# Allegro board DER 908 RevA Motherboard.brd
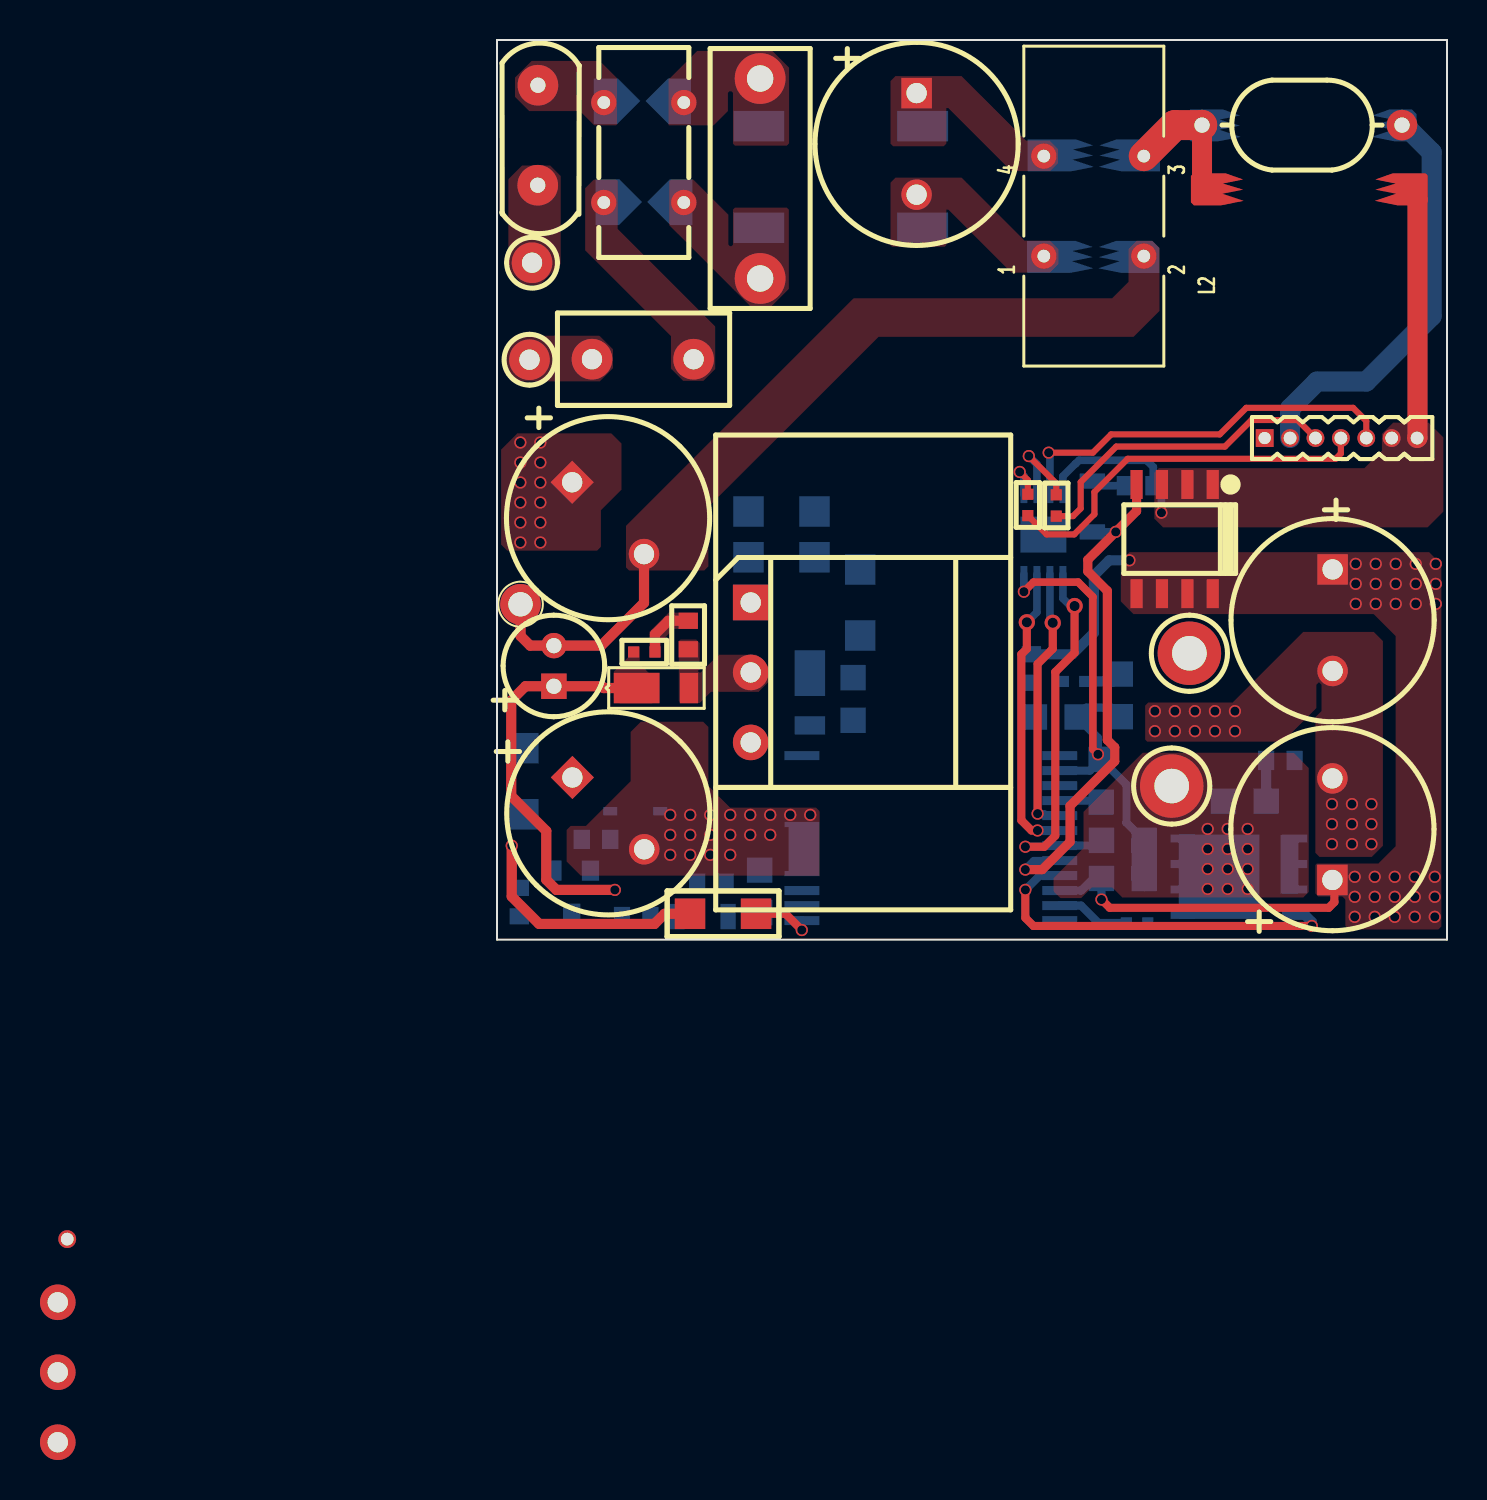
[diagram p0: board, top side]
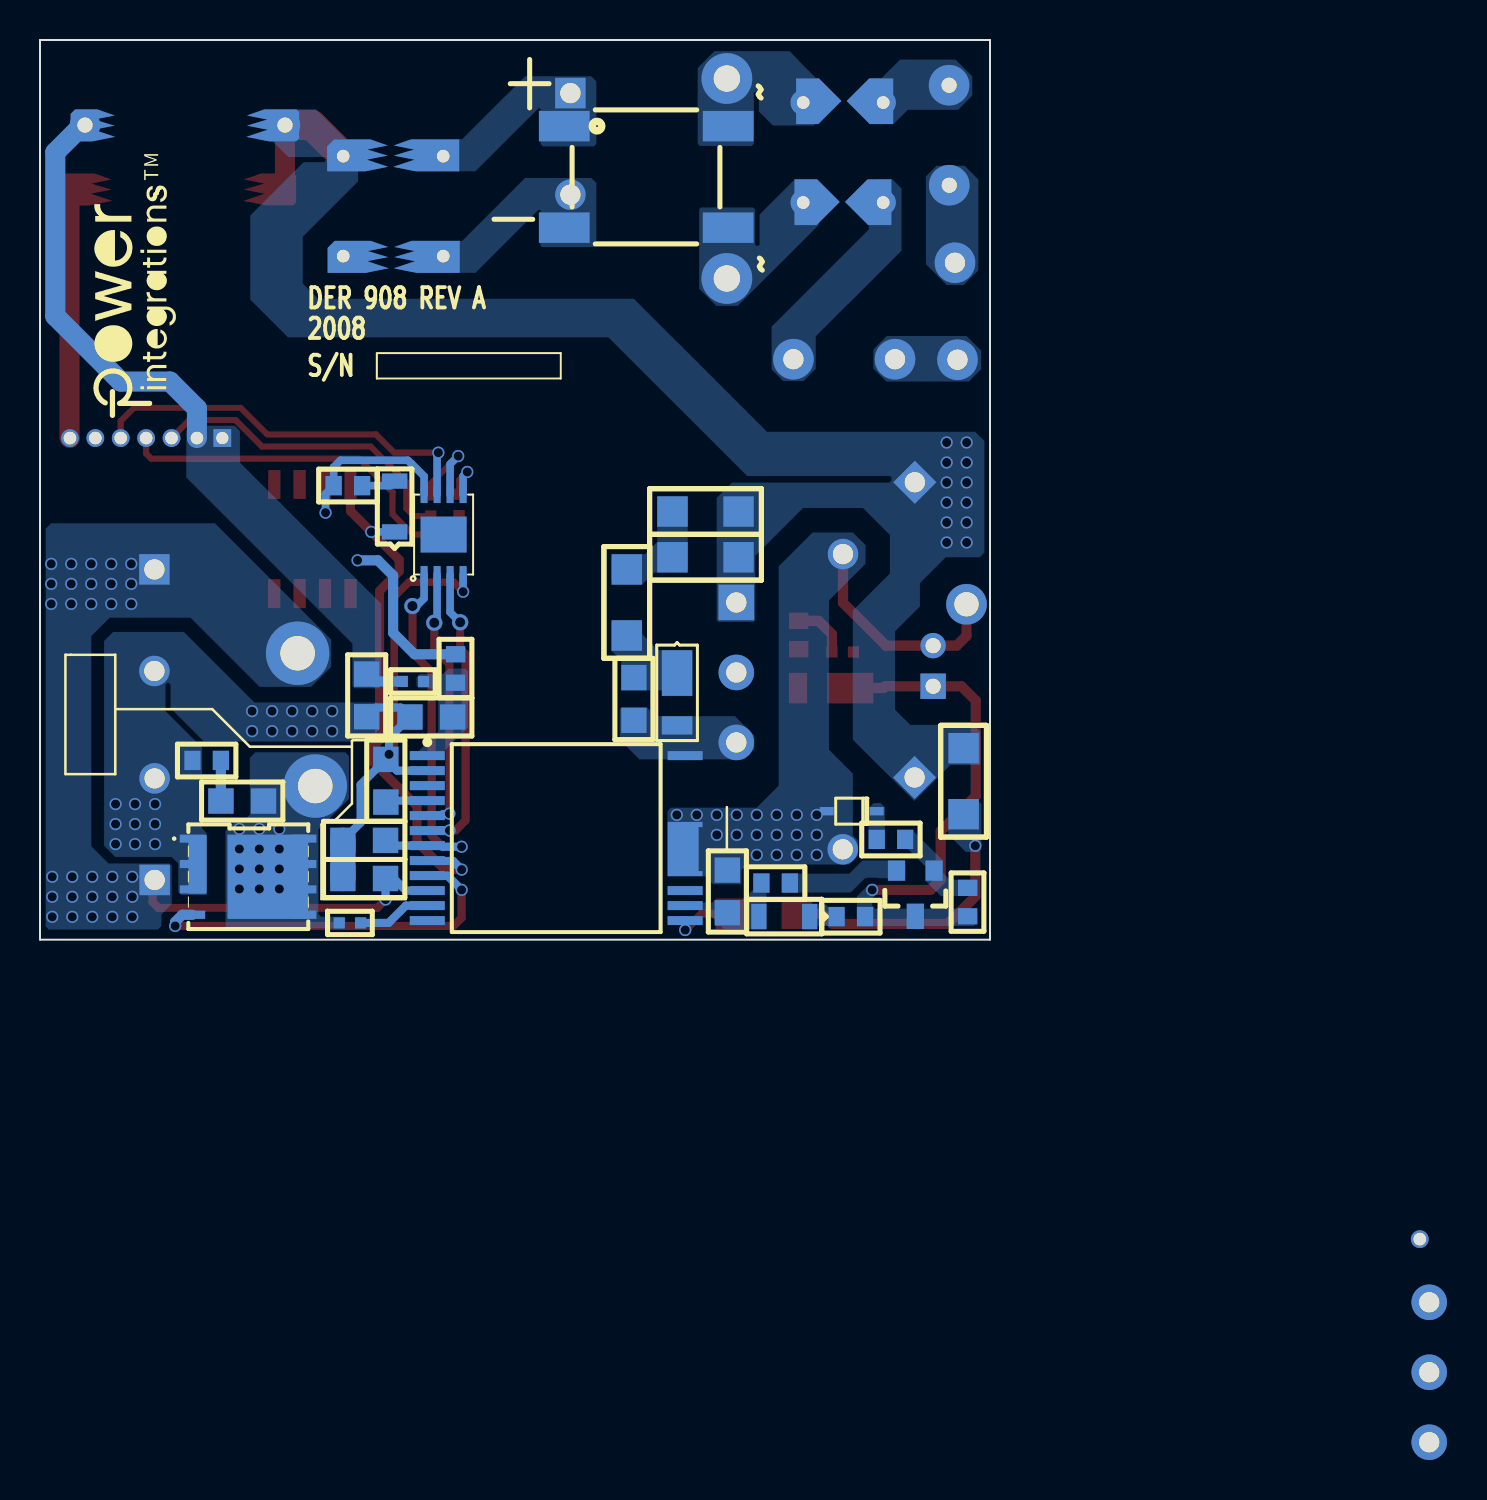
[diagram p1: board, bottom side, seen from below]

Outline 47.5 x 45 mm; copper layers: TOP, BOTTOM. Coordinates in mm from the lower left corner of the outline.
Outline path: 0,45 0,0 47.5,0 47.5,45 0,45

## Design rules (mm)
constraint set DEFAULT: min track width 0.508

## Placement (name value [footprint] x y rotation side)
BR1  TBS30M-TP  [PISMD_4-TBS]  21.73 40.69 90 bottom
C1  0.1 uF  [PINPXCAPRAD5X13X11P1MM040]  13.16 33.07 90 top
C2  15 uF  [PIPOLCAPCYLD400LS200040]  20.98 42.34 270 top
C3  15 uF  [PIPOLCAPCYLD400LS200040]  3.76 22.88 315 top
C4  15 uF  [PIPOLCAPCYLD400LS200040]  3.77 8.11 315 top
C5  22  uF  [PIPOLCAPCLYD200LS80030]  2.84 12.67 90 top
C6  2.2 nF  [PISMC1206]  15.88 21.41 180 bottom
C7  47 pF  [PISMC0805]  17.81 13.11 270 bottom
C8  56 pF  [PISMC0603]  9.56 15.95 270 top
C9  4.7 uF  [PISMC0805]  13.13 1.35 90 bottom
C10  470 pF  [PINPCAPRAD7MMXLS10MM030]  35.25 40.74 0 top
C11  470 uF  [PIPOLCAPCYLD400LS200040]  41.77 2.99 90 top
C12  470 uF  [PIPOLCAPCYLD400LS200040]  41.78 18.52 270 top
C13  1000 pF  [PISMC0603]  39.88 8.97 180 bottom
C14  2.2 uF  [PISMC0805]  30.21 9.02 270 bottom
C15  4.7 uF  [PISMC0805]  29 11.14 180 bottom
C16  2.2 uF  [PISMC0805]  32.36 3.06 180 bottom
C17  2.2 uF  [PISMC0805]  32.36 4.97 180 bottom
D1  DFLR1200-7  [PISMDDFLR120012]  6.96 12.59 180 top
D2  DFLR1600-7  [PISMDDFLR120012]  15.65 13.36 90 bottom
D3  BAV21WS-7-F  [PISMSOD323]  29.77 20.4 90 bottom
F1  2 A  [PI_RST_MICROFUSE]  9.83 29.03 180 top
FL1  Hole_70mils  [PI_HOLE_70MIL]  34.62 14.3 0 top
FL2  Hole_70mils  [PI_HOLE_70MIL]  33.74 7.66 0 top
FL3  Hole_50mils  [PI_HOLE_50MIL]  1.18 16.77 0 top
J2  CON8  [PI_HDR_1P27MM_8PIN]  38.38 25.09 0 top
L1  750 uH  [PI_4P_LS5W4P5XD10P5MMD40]  7.34 39.37 0 top
L2  19.8 mH  [PI_TOROID_CMC15X7_12_34V]  26.34 34.19 90 top
NOREF  -  []  -150.78 54.23 0 top
NOREF#2  -  []  -228.6 -144.78 0 top
NOREF#3  -  []  0 45 0 top
NOREF#4  -  []  47.5 0 90 top
NOREF#5  -  []  45.26 26.11 90 bottom
Q1  MMBTA06LT1G  [PISMSOT23123_1]  4.67 3.45 0 bottom
Q2  AONS62922  [PISMPQFN5X6B]  39.88 5.05 270 bottom
Q3  AO4354  [PISMSO8]  35.79 22.77 180 top
R1  2.00 M  [PISMR1206]  1.32 6.27 90 bottom
R2  1.80 M  [PISMR1206]  12.95 1.3 180 top
R3  1.00 M  [PISMR1206]  12.57 19.13 0 bottom
R4  4.7  [PISMR1206]  18.16 15.21 90 bottom
R5  100  [PISMR0402]  6.83 14.39 0 top
R6  64.9 k  [PISMR0603]  1.12 2.59 270 bottom
R7  0.0  [PISMR0603]  5.66 5.02 180 bottom
R8  2.55 k  [PISMR0603]  11.43 2.83 180 bottom
R9  47  [PISMR0603]  7.67 1.16 180 bottom
R10  47  [PISMR0402]  32.54 0.84 180 bottom
R11  10  [PISMR0805]  38.46 6.93 180 bottom
R12  0.009  [PISMR0805]  31.17 11.15 90 bottom
R13  422 k (DNP)  [PISMR0603]  26.72 14.27 270 bottom
R14  10  [PISMR0402]  29.39 12.92 180 bottom
R15  100  [PISMR0603]  31.39 22.71 0 bottom
R16  22  [PISMR0402]  27.97 21.18 90 top
R17  22  [PISMR0402]  26.54 21.21 90 top
RT1  2.5  [PI_RAD150X300LS200D030]  2.04 37.73 89.9 top
T1  ATQ23.7/14  [PI_BOBBIN_ATQ23_7_H_6P]  18.31 13.37 0 top
TP1  WHT  [PITPKEYSTONE100X100]  1.63 29.01 0 top
TP2  BLK  [PITPKEYSTONE100X100]  1.75 33.86 270 top
U1  INN3378C-H302  [PI_IC_INSOP_24D]  28.14 9.21 180 bottom
U2  VP302  [PI_SM_DFN-8]  28.3 18.26 180 bottom
VR1  MM3Z9V1C  [PISMSOD323F]  5.66 6.43 0 bottom
VR2  BZX384-C36,115  [PISMSOD323]  9.02 1.16 0 bottom

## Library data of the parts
BR1 = DIODE BRIDGE_+-~~
C1 = CAP NP: alternate symbols: (pinpxcaprad5x13x11p1mm040h)
C2-C4 = CAP POL: alternate symbols: (pipolcapcyld400ls200040800h)
C5 = CAP POL: alternate symbols: (pipolcapclyd200ls80030h)
C6-C10 C13-C17 = CAP NP
C11 C12 = CAP POL
D1-D3 = DIODE
F1 = FUSE: alternate symbols: (pirstmicrofusehoz)
FL1-FL3 = FlyingLead
J2 = CON8
L1 L2 = TORRID 4P_12_43a
Q1 = NPN_BEC
Q2 Q3 = FET_N_SGD_123_4_5678
R1-R8 R10-R17 = R
R9 = R: alternate symbols: (pismr0603_1)
RT1 = THERMISTOR: alternate symbols: (pirad400x300ls200040_h)
T1 = BATQ23_7_6P/GENERIC
TP1 TP2 = TESTPOINT
U1 = InnoPro_p15
U2 = VP302
VR1 VR2 = DIODE_ZENER

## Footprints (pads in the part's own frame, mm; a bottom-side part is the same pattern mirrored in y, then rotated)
PI_4P_LS5W4P5XD10P5MMD40
  round 1.27 hole 0.635: 1(-2,-2.5) 2(2,-2.5) 3(2,2.5) 4(-2,2.5)
PI_BOBBIN_ATQ23_7_H_6P
  rect 1.778x1.778 hole 1.016: 1(-5.626,3.5)
  round 1.778 hole 1.016: 2(-5.626,0) 3(-5.626,-3.5) 4(-40.272,-38.501) 5(-40.272,-35.001) 6(-40.272,-31.501)
PI_HDR_1P27MM_8PIN
  rect 0.889x0.889 hole 0.61: 1(0,0)
  round 0.889 hole 0.635: 2(1.27,0) 3(2.54,0) 4(3.81,0) 5(5.08,0) 6(6.35,0) 7(7.62,0) 8(-59.873,-40.066)
PI_HOLE_50MIL
  round 2.032 hole 1.219: 1(0,0)
PI_HOLE_70MIL
  round 3.175 hole 1.727: 1(0,0.025)
PI_IC_INSOP_24D
  rect 1.75x0.45 smd: 1(0,0) 2(0,-0.749) 3(0,-1.501) 4(0,-2.25) 5(0,-3) 6(0,-3.749) 7(0,-4.501) 8(0,-5.25) 9(0,-6) 10(0,-6.749) 11(0,-7.501) 12(0,-8.25) 13(12.89,-8.25) 14(12.89,-7.501) 15(12.89,-6.749) 24(12.89,0)
  custom 0.437x0.437 smd: 16(12.89,-4.671)
PI_RAD150X300LS200D030
  round 2.032 hole 0.762: 1(0,0) 2(5.001,0)
PI_RST_MICROFUSE
  round 2.032 hole 1.016: 1(0,0) 2(5.08,0)
PI_SM_DFN-8
  rect 0.35x0.851 smd: 1(0,0) 2(0.65,0) 3(1.301,0) 4(1.951,0) 5(1.951,4) 6(1.301,4) 7(0.65,4) 8(0,4)
  rect 2.301x1.801 smd: 9(0.975,1.999)
PI_TOROID_CMC15X7_12_34V
  round 1.27 hole 0.635: 1(0,-1) 2(0,-6) 3(5,-6) 4(5,-1)
PINPCAPRAD7MMXLS10MM030
  round 1.524 hole 0.762: 1(0,0) 2(10,0)
PINPXCAPRAD5X13X11P1MM040
  round 2.54 hole 1.321: 1(0,0) 2(10,0)
PIPOLCAPCLYD200LS80030
  rect 1.27x1.27 hole 0.762: 1(0,0)
  round 1.27 hole 0.762: 2(2.032,0)
PIPOLCAPCYLD400LS200040
  rect 1.524x1.524 hole 1.016: 1(0,0)
  round 1.524 hole 1.016: 2(5.08,0)
PISMC0603
  rect 0.813x0.965 smd: 1(0,0) 2(1.422,0)
PISMC0805
  rect 1.27x1.27 smd: 1(0,0) 2(2.134,0)
PISMC1206
  rect 1.524x1.524 smd: 1(0,0) 2(3.302,0)
PISMD_4-TBS
  rect 1.524x2.54 smd: 1(0,-0.449) 2(-5.08,-0.449) 3(0,-8.644) 4(-5.08,-8.644)
PISMDDFLR120012
  rect 2.286x1.524 smd: 1(-0.025,0)
  rect 0.914x1.524 smd: 2(-2.642,0)
PISMPQFN5X6B
  rect 0.406x1.27 smd: 1(0,0) 2(1.27,0) 3(2.54,0) 4(3.81,0)
  rect 0.406x1.219 smd: 5(3.81,5.588) 6(2.54,5.588) 7(1.27,5.588) 8(0,5.588)
PISMR0402
  rect 0.559x0.559 smd: 1(0,0) 2(1.067,0)
PISMR0603
  rect 0.813x0.965 smd: 1(0,0) 2(1.422,0)
PISMR0805
  rect 1.27x1.27 smd: 1(0,0) 2(2.134,0)
PISMR1206
  rect 1.524x1.524 smd: 1(0,0) 2(3.302,0)
PISMSO8
  rect 0.61x1.448 smd: 1(0,0) 2(1.27,0) 3(2.54,0) 4(3.81,0) 5(3.81,5.461) 6(2.54,5.461) 7(1.27,5.461) 8(0,5.461)
PISMSOD323
  rect 0.762x1.27 smd: 1(0,0) 2(2.54,0)
PISMSOD323F
  rect 0.701x0.419 smd: 1(0,0) 2(2.5,0)
PISMSOT23123_1
  rect 0.864x1.016 smd: 1(-1.88,0) 2(0,0)
  rect 0.864x1.27 smd: 3(-0.94,2.286)
PITPKEYSTONE100X100
  round 2.032 hole 1.016: 1(0,0)

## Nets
VBUS: J2.6 J2.7 Q3.1 Q3.2 Q3.3(S3) R15.2 U2.8
CC1: J2.3 R16.1
CC2: J2.4 R17.1
NC3: U1.3
NTC: J2.5 U2.7
RTN: C10.2 J2.1 J2.2 R12.2 R14.1
S: C11.2 C12.2 C13.1 C14.1 C15.1 C16.1 C17.1 Q2.1 Q2.2 Q2.3(S3) R12.1 U1.2 U2.4
V-PIN: R2.1 U1.13
N12237519: F1.2 TP1.1
N12237523: RT1.1 TP2.1
N12237527: BR1.1 C2.1 L2.4
N12237547: C3.1 C4.1 C6.2 C10.1 L2.3 R1.2 R3.1 T1.1
N12237619: F1.1 L1.1
N12237623: L1.4 RT1.2
N12237649: BR1.3 C1.2 L1.3
N12237657: BR1.4 C1.1 L1.2
N12237771: BR1.2 C2.2 L2.1
N12237803: C3.2 C4.2 C5.2 C9.2 FL3.1 L2.2 U1.16 VR1.2
N12645578: C5.1 D1.1 Q1.3 R5.1 R6.2 R9.2
N12645654: Q1.1 R6.1 R7.2
N12645698: R7.1 VR1.1
N12646808: Q1.2(EMITTER) R8.2
N12647032: C8.2 D1.2 T1.2
N12647250: C7.2 D2.2 T1.3 U1.24
N12647255: C7.1 D2.1 R4.1
N12647291: C6.1 R3.2 R4.2
N12648519: C8.1 R5.2
N12649378: C9.1 R8.1 U1.14 VR2.2
N12649481: R9.1 VR2.1
N12651364: R1.1 R2.2
N12652887: C11.1 C12.1 C16.2 FL1.1 Q3.5 Q3.6 Q3.7 Q3.8 R13.1 U1.10(VOUT)
N12652989: D3.1 Q3.4 U1.8
N12653013: D3.2 R15.1
N12653157: FL2.1 Q2.5 Q2.6 Q2.7 Q2.8 R10.1 R11.2
N12653279: Q2.4 U1.9
N12653331: R10.2 U1.11
N12653381: C15.2 R13.2 R14.2 U1.1
N12665660: C17.2 U1.7 U2.1(VCC)
N12665712: R16.2 U2.6
N12665748: R17.2 U2.5
N12666228: U1.5 U2.2
N12666235: U1.6 U2.3
N12666360: C14.2 U1.4
N12689323: C13.2 R11.1

Pads without a net: J2 8; T1 4 5 6; U1 12 15; U2 9

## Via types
v1: diameter 0.61, hole 0.457, TOP to BOTTOM, 109 vias
v2: diameter 0.813, hole 0.508, TOP to BOTTOM, 3 vias

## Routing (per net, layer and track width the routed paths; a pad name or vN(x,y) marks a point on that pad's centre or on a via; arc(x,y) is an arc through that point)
VBUS: length 21
  TOP w1: J2.7 46.02,25.11 46.02,37.03 45.57,37.49
  BOTTOM w0.381: U2.8 28.3,23.18 28.93,23.81 28.94,23.81 29.11,23.98 32.48,23.98 32.82,23.64 R15.2 33.22,22.3 v1(33.22,21.36)
CC1: length 16.1
  TOP w0.305: J2.3 40.92,25.09 40.03,25.99 37.73,25.99 36.4,24.66 30.96,24.66 29.18,22.89 29.18,21.56 28.8,21.18 R16.1
CC2: length 19.1
  TOP w0.305: R17.1 27.48,20.27 28.86,20.27 29.87,21.28 29.87,22.39 31.54,24.05 41.93,24.05 42.19,24.31 J2.4
NTC: length 20.1
  TOP w0.305: v1(27.58,24.36) 29.79,24.36 30.71,25.27 36.14,25.27 37.47,26.6 42.8,26.6 43.46,25.94 J2.5
  BOTTOM w0.381: U2.7 27.65,24.3 v1(27.58,24.36)
RTN: length 22.5
  BOTTOM w0.508: R12.2 30.8,12.92 R14.1
  BOTTOM w1: J2.2 39.65,26.57 41,27.91 43.46,27.91 46.74,31.19 46.74,39.38 45.4,40.71
S: length 27.1
  TOP w0.381: v1(26.34,17.4) 26.82,17.88 29.06,17.88 29.79,17.14 29.79,9.53 v1(30.05,9.27)
  BOTTOM w0.381: U2.4 v1(26.34,17.4)
  BOTTOM w0.406: C14.1 29.65,8.45 28.14,8.45 U1.2 ; C14.1 31.47,7.75 31.47,5.85 C17.1 ; C14.1 30.21,9.11 v1(30.05,9.27) 30.05,10.09 C15.1 29,11.15 29.46,11.61 30.71,11.61 R12.1
  BOTTOM w1.27: C17.1 C16.1
  vias: v1(32.89,11.43) v1(32.89,10.43) v1(33.89,11.43) v1(33.89,10.43) v1(34.89,11.43) v1(34.89,10.43) v1(35.9,11.43) v1(35.9,10.43) v1(36.9,11.43) v1(36.9,10.43) v1(41.75,6.78) v1(41.75,5.78) v1(41.75,4.78) v1(42.75,6.78) v1(42.75,5.78) v1(42.75,4.78) v1(43.72,6.78) v1(43.72,5.78) v1(43.72,4.78)
V-PIN: length 3.1
  TOP w0.406: v1(15.24,0.48) 14.43,1.3 R2.1
  BOTTOM w0.406: U1.13 15.25,0.95 15.25,0.95 15.25,0.49 v1(15.24,0.48)
N12237547: length 6.9
  TOP w1: C10.1 35.25,37.98 35.66,37.57
  TOP w1.5: C10.1 33.89,40.74 L2.3
  vias: v1(1.17,24.87) v1(1.17,23.87) v1(1.17,22.87) v1(1.17,21.87) v1(1.17,20.87) v1(1.17,19.87) v1(2.17,24.87) v1(2.17,23.87) v1(2.17,22.87) v1(2.17,21.87) v1(2.17,20.87) v1(2.17,19.87)
N12237803: length 11.3
  TOP w0.508: C3.2 7.35,19.29 7.35,16.85 5.21,14.71 C5.2 1.66,14.71 1.18,15.19 FL3.1
  vias: v1(8.66,6.24) v1(8.66,5.24) v1(8.66,4.24) v1(9.66,6.24) v1(9.66,5.24) v1(9.66,4.24) v1(10.66,6.24) v1(10.66,5.24) v1(10.66,4.24) v1(11.66,6.24) v1(11.66,5.24) v1(11.66,4.24) v1(12.66,6.24) v1(12.66,5.24) v1(13.66,6.24) v1(13.66,5.24) v1(14.66,6.24) v1(15.66,6.24)
N12645578: length 19.9
  TOP w0.508: v1(5.89,2.49) 2.97,2.49 2.46,3 2.46,5.44 0.71,7.19 0.71,11.96 1.42,12.67 C5.1 5.24,12.67 5.33,12.59 D1.1
N12648519: length 2.8
  TOP w0.508: C8.1 8.57,15.95 7.9,15.28 R5.2
N12651364: length 12.2
  TOP w0.508: R2.2 8.38,1.3 7.87,0.79 2.11,0.79 0.74,2.16 v1(0.74,4.7)
N12652887: length 25
  TOP w0.406: v1(30.22,2.01) 30.64,1.59 41.58,1.59 41.87,1.88 41.87,2.89 C11.1
  BOTTOM w0.406: v1(30.22,2.01) C16.2 29.81,3.06 29.21,2.46 U1.10
  BOTTOM w0.508: v1(31.62,18.97) 30.61,18.97 29.84,18.21 29.84,15.35 28.77,14.27 R13.1
  vias: v1(42.94,18.8) v1(42.94,17.8) v1(42.94,16.79) v1(42.89,3.14) v1(42.89,2.14) v1(42.89,1.14) v1(43.94,18.8) v1(43.94,17.8) v1(43.94,16.79) v1(43.89,3.14) v1(43.89,2.14) v1(43.89,1.14) v1(44.94,18.8) v1(44.94,17.8) v1(44.94,16.79) v1(44.89,3.14) v1(44.89,2.14) v1(44.89,1.14) v1(45.94,18.8) v1(45.94,17.8) v1(45.94,16.79) v1(45.89,3.14) v1(45.89,2.14) v1(45.89,1.14) v1(46.94,18.8) v1(46.94,17.8) v1(46.94,16.79) v1(46.89,3.14) v1(46.89,2.14) v1(46.89,1.14)
N12652989: length 26.3
  TOP w0.457: Q3.4 31.98,21.44 v1(30.94,20.4) 29.54,19 29.54,18.42 30.52,17.44 30.52,9.99 30.89,9.62 30.89,8.92 28.65,6.69 28.65,4.89 27.26,3.51 v1(26.42,3.51)
  BOTTOM w0.381: D3.1 v1(30.94,20.4)
  BOTTOM w0.406: U1.8 28.12,3.94 27.66,3.94 27.66,3.94 26.85,3.94 v1(26.42,3.51)
N12653013: length 1.7
  BOTTOM w0.381: D3.2 30,22.71 R15.1
N12653157:
  vias: v1(35.53,5.54) v1(35.53,4.54) v1(35.53,3.54) v1(35.53,2.54) v1(36.54,5.54) v1(36.54,4.54) v1(36.54,3.54) v1(36.54,2.54) v1(37.53,5.54) v1(37.53,4.54) v1(37.53,3.54) v1(37.53,2.54)
N12653279: length 19.1
  TOP w0.406: v1(40.74,0.69) 26.82,0.69 26.42,1.09 v1(26.42,2.49)
  BOTTOM w0.406: U1.9 28.13,3.2 27.13,3.2 v1(26.42,2.49)
  BOTTOM w0.508: v1(40.74,0.69) 40.74,0.89 40.39,1.24 Q2.4
N12653331: length 3.7
  BOTTOM w0.406: R10.2 30.07,0.84 29.2,1.7 U1.11
N12665660: length 19.5
  TOP w0.406: v1(26.42,4.65) 27.36,4.65 27.91,5.2 27.91,13.39 28.88,14.35 v2(28.88,16.69)
  BOTTOM w0.381: U2.1 28.3,17.07 28.68,16.69 v2(28.88,16.69)
  BOTTOM w0.406: C17.2 29.96,4.7 U1.7 28.12,4.69 27.4,4.69 27.36,4.65 v1(26.42,4.65)
N12665712: length 4.6
  TOP w0.305: R16.2 27.97,22.81 v1(26.59,24.19)
  BOTTOM w0.381: v1(26.59,24.19) 27,23.78 U2.6
N12665748: length 2.5
  TOP w0.305: v1(26.14,23.39) 26.54,22.99 R17.2
  BOTTOM w0.381: v1(26.14,23.39) 26.34,23.19 U2.5
N12666228: length 13.5
  TOP w0.406: v1(27.03,6.3) 27.03,13.79 27.79,14.55 v2(27.79,15.85)
  BOTTOM w0.381: U2.2 27.65,15.99 v2(27.79,15.85)
  BOTTOM w0.406: v1(27.03,6.3) 27.06,6.27 27.36,6.27 27.43,6.21 U1.5
N12666235: length 14.7
  TOP w0.406: v1(27.03,5.46) 26.73,5.46 26.22,5.97 26.22,14.27 26.49,14.55 v2(26.49,15.88)
  BOTTOM w0.381: U2.3 27,16.38 v2(26.49,15.88)
  BOTTOM w0.406: U1.6 27.03,5.46 v1(27.03,5.46)
N12666360: length 2.1
  BOTTOM w0.406: U1.4 30.14,6.95 C14.2
N12689323: length 2
  BOTTOM w0.508: R11.1 C13.2

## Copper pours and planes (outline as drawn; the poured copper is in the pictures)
VBUS on TOP (solid shape): 46.53,38.23 46.53,36.88 46.38,36.73 45.04,36.73 43.89,36.95 44.96,37.31 43.92,37.51 44.93,37.82 43.92,38.02 44.78,38.33 46.43,38.33
VBUS on TOP: 32.87,23.36 32.87,21.06 33.3,20.62 46.53,20.62 47.32,21.41 47.32,25.12 46.58,25.86 44.81,25.86 44.25,25.3 44.25,24.46 43.37,23.58 33.1,23.58
RTN on BOTTOM (solid shape): 45.97,41.3 45.97,40.13 45.77,39.93 45.77,39.93 44.88,39.93 43.74,40.15 44.81,40.51 43.77,40.71 44.78,41.02 43.77,41.22 44.63,41.53 45.74,41.53
RTN on BOTTOM: 31.78,12.57 31.88,12.67 31.88,14.81 40.18,23.11 40.18,25.45 39.93,25.7 37.77,25.7 37.5,25.44 37.5,23.86 30.43,16.79 30.43,12.7 30.56,12.57
S on BOTTOM (solid shape): 40.08,2.31 39.17,2.31 39.17,5.23 40.08,5.23
S on TOP: 40.92,11.13 40.92,4.34 41.12,4.14 43.74,4.14 44.3,4.7 44.3,14.94 43.84,15.39 40.31,15.39 36.78,11.86 32.56,11.86 32.41,11.71 32.41,10.01 32.51,9.91 39.29,9.91 40.97,11.58 40.97,12.75 41.1,12.88 41.22,12.75 41.22,11.43
S on BOTTOM: 39.17,2.24 40.44,2.24 40.59,2.39 40.59,3.81 40.92,4.14 43.74,4.14 44.3,4.7 44.3,14.94 43.84,15.39 40.31,15.39 36.78,11.86 30.53,11.86 30.53,10.52 31.14,9.91 39.29,9.91 40.97,11.58 40.97,12.75 41.1,12.88 41.22,12.75 41.22,11.43 39.4,9.6 39.4,5.56 39.17,5.33
N12237519 on TOP: 1.14,30.21 0.41,29.48 0.41,28.54 1.02,27.93 5.14,27.93 5.8,28.58 5.8,29.52 5.12,30.21
N12237519 on BOTTOM: 1.17,30.19 0.44,29.46 0.44,28.53 1.06,27.91 5.18,27.91 5.84,28.57 5.84,29.51 5.16,30.19
N12237523 on TOP: 2.65,38.72 1.26,38.72 0.57,38.04 0.57,33.49 1.31,32.75 2.15,32.75 3.19,33.79 3.19,38.19
N12237523 on BOTTOM: 2.67,38.71 1.27,38.71 0.58,38.02 0.58,33.48 1.32,32.74 2.16,32.74 3.2,33.78 3.2,38.18
N12237527 on BOTTOM (solid shape): 29.81,39.72 28.8,39.52 29.81,39.22 28.77,39.01 29.84,38.66 28.69,38.43 26.53,38.43 26.53,40.03 28.95,40.03
N12237527 on TOP: 22.47,41.59 22.57,41.59 25.72,38.44 27.67,38.44 28.05,38.82 28.05,39.54 27.62,39.97 26.45,39.97 23.23,43.19 19.93,43.19 19.67,42.94 19.67,39.81 19.8,39.69 22.34,39.69 22.47,39.81
N12237527 on BOTTOM: 22.48,41.58 22.58,41.58 25.73,38.43 27.71,38.43 28.09,38.81 28.09,39.52 27.58,40.03 26.39,40.03 23.24,43.18 19.94,43.18 19.68,42.93 19.68,39.8 19.81,39.67 22.35,39.67 22.48,39.8
N12237547 on TOP (solid shape): 37.31,38.02 36.29,37.82 37.31,37.51 36.26,37.31 37.33,36.95 36.19,36.73 34.85,36.73 34.7,36.88 34.7,38.2 34.7,38.2 34.82,38.33 36.44,38.33
N12237547 on BOTTOM (solid shape): 33.15,39.67 33.15,38.43 31.23,38.43 30.09,38.66 31.16,39.01 30.11,39.22 31.13,39.52 30.11,39.72 30.98,40.03 32.79,40.03
N12237547 on BOTTOM (solid shape): 37.15,41.22 36.14,41.02 37.15,40.71 36.11,40.51 37.18,40.15 36.04,39.93 34.7,39.93 34.54,40.08 34.54,41.4 34.55,41.4 34.67,41.53 36.29,41.53
N12237547 on TOP: 5.19,21.48 5.19,19.65 5,19.46 0.51,19.46 0.2,19.76 0.2,24.51 1.02,25.32 5.71,25.32 6.22,24.82 6.22,22.5
N12237547 on BOTTOM: 0.48,10.39 0.48,8.79 0.53,8.74 1.98,8.74 3.78,6.93 6.86,10.01 6.86,16.46 5,18.31 5,20.24 6.35,21.59 9.35,21.59 11.73,19.2 11.73,15.98 11.81,15.9 13.59,15.9 13.67,15.98 13.67,22.1 12.9,22.86 5.03,22.86 4.93,22.96 4.93,23.11 5,23.19 12.14,23.19 19.08,30.12 35.1,30.12 36.98,32 36.98,36.22 34.32,38.89 33.3,38.89 33.17,39.01 33.17,39.07 33.25,39.14 35.08,39.14 36.02,40.08 36.02,41.15 35.64,41.53 33.71,41.53 31.6,39.42 31.6,37.92 34.37,35.15 34.37,32.82 33.6,32.05 17.81,32.05 11.15,25.4 0.74,25.4 0.28,24.94 0.28,19.35 0.51,19.13 2.21,19.13 3.51,17.83 3.51,16.66 4.75,15.42 4.75,11.51 3.99,10.74 0.84,10.74
N12237619 on BOTTOM (solid shape): 7.25,36.9 6.1,35.74 4.93,35.74 4.93,38.03 6.12,38.03
N12237619 on TOP: 6.03,35.55 6.03,37.96 5.98,38.01 4.84,38.01 4.41,37.58 4.41,34.48 8.7,30.19 8.7,28.56 9.31,27.95 10.33,27.95 10.91,28.54 10.91,30.67
N12237619 on BOTTOM: 6.06,35.52 6.06,37.58 5.61,38.02 4.88,38.02 4.42,37.57 4.42,34.47 8.71,30.18 8.71,28.55 9.32,27.94 10.34,27.94 10.92,28.52 10.92,30.66
N12237623 on BOTTOM (solid shape): 7.17,41.95 6.01,40.79 4.84,40.79 4.84,43.08 6.04,43.08
N12237623 on TOP: 1.74,43.95 5.14,43.95 6.01,43.08 6.01,40.78 5.96,40.73 4.86,40.73 4.15,41.44 1.61,41.44 0.9,42.15 0.9,43.12
N12237623 on BOTTOM: 1.73,44.02 4.5,44.02 6.07,42.44 6.07,40.89 5.97,40.79 4.83,40.79 4.11,41.5 1.6,41.5 0.89,42.21 0.89,43.18
N12237649 on BOTTOM (solid shape): 9.69,40.79 8.58,40.79 7.43,41.95 8.56,43.08 9.69,43.08
N12237649 on TOP: 10.83,40.73 11.54,41.44 11.54,42.35 11.62,42.43 11.72,42.43 11.8,42.35 11.8,39.81 11.9,39.71 14.49,39.71 14.61,39.83 14.61,43.61 13.77,44.45 10.01,44.45 8.57,43.01 8.57,40.75 8.6,40.73
N12237649 on BOTTOM: 10.85,40.72 11.56,41.43 11.56,42.34 11.63,42.42 11.73,42.42 11.81,42.34 11.81,39.8 11.91,39.7 14.5,39.7 14.62,39.81 14.62,43.6 13.78,44.44 10.02,44.44 9.59,44.01 9.6,43.99 8.59,42.98 8.59,40.94 8.81,40.72
N12237657 on BOTTOM (solid shape): 9.78,35.74 8.67,35.74 7.51,36.9 8.64,38.03 9.78,38.03
N12237657 on TOP: 8.61,35.74 12.66,31.69 13.73,31.69 14.59,32.55 14.59,36.51 14.49,36.61 11.9,36.61 11.8,36.51 11.8,34.76 11.72,34.68 11.65,34.68 11.57,34.76 11.57,36.26 9.82,38.01 8.7,38.01 8.61,37.92
N12237657 on BOTTOM: 8.56,35.75 12.61,31.7 13.68,31.7 14.54,32.56 14.54,36.53 14.44,36.63 11.85,36.63 11.75,36.53 11.75,34.77 11.67,34.7 11.6,34.7 11.52,34.77 11.52,36.27 9.77,38.02 8.65,38.02 8.56,37.94
N12237771 on BOTTOM (solid shape): 29.79,34.65 28.77,34.44 29.79,34.14 28.74,33.93 29.81,33.58 28.67,33.35 26.51,33.35 26.51,34.95 28.92,34.95
N12237771 on TOP: 22.39,34.66 22.47,34.73 22.47,36.51 22.57,36.51 25.72,33.36 27.65,33.36 28.08,33.79 28.08,34.53 27.65,34.96 26.38,34.96 23.23,38.11 19.93,38.11 19.67,37.86 19.67,34.73 19.75,34.66
N12237771 on BOTTOM: 22.4,34.65 22.48,34.72 22.48,36.5 22.58,36.5 25.73,33.35 27.66,33.35 28.09,33.78 28.09,34.52 27.66,34.95 26.39,34.95 23.24,38.1 19.94,38.1 19.68,37.85 19.68,34.72 19.76,34.65
N12237803 on BOTTOM (solid shape): 33.12,34.59 33.12,33.35 31.21,33.35 30.06,33.58 31.13,33.93 30.09,34.14 31.1,34.44 30.09,34.65 30.95,34.95 32.77,34.95
N12237803 on TOP: 30.76,32.08 31.57,32.89 31.57,34.54 31.98,34.95 32.77,34.95 33.12,34.59 33.12,31.45 31.83,30.15 19.08,30.15 10.57,21.64 10.57,18.67 10.36,18.47 6.6,18.47 6.45,18.62 6.45,20.7 17.83,32.08
N12237803 on TOP: 16.13,3.2 4.19,3.2 3.48,3.91 3.48,5.49 3.68,5.69 4.45,5.69 6.68,7.92 6.68,10.39 7.19,10.9 10.31,10.9 10.57,10.64 10.57,7.7 11.66,6.6 15.95,6.6 16.13,6.43
N12237803 on BOTTOM: 14.25,3.17 13.84,2.77 12.42,2.77 12.42,3.48 12.14,3.76 7.04,3.76 6.6,4.19 6.6,4.95 6.86,5.21 6.86,8.31 8.05,9.5 8.05,16.97 6.22,18.8 6.22,19.74 6.86,20.37 8.86,20.37 10.57,18.67 10.57,7.7 11.66,6.6 15.95,6.6 16.13,6.43 16.13,3.17
N12645578 on TOP: 6.65,14.68 7.09,14.68 7.14,14.63 7.14,13.79 8.1,12.83 8.1,12.17 7.75,11.81 6.15,11.81 5.84,12.12 5.84,13.41 6.55,14.12 6.55,14.58
N12645578 on BOTTOM: 5.59,2.36 5.59,2.62 5.77,2.79 6.02,2.79 6.65,2.16 6.65,0.84 6.5,0.69 0.81,0.69 0.64,0.86 0.64,1.37 0.81,1.55 5.74,1.55 5.89,1.7 5.89,2.06
N12645654 on BOTTOM: 3.89,5.49 4.55,5.49 4.65,5.38 4.65,4.72 4.47,4.55 4.11,4.55 3.23,3.66 3.23,2.95 2.46,2.18 0.79,2.18 0.64,2.34 0.64,2.82 0.81,3 2.01,3 2.36,3.35 2.36,3.96
N12645698 on BOTTOM: 5.46,6.83 5.82,6.83 6.07,6.58 6.07,4.72 5.89,4.55 5.41,4.55 5.26,4.7 5.26,6.63
N12646808 on BOTTOM: 4.24,3.23 4.39,3.07 6.25,3.07 6.96,2.36 10.16,2.36 10.41,2.62 10.41,3.07 10.19,3.3 7.04,3.3 6.38,3.96 4.47,3.96 4.24,3.73
N12647032 on TOP: 9.09,14.94 9.09,11.94 9.19,11.84 10.13,11.84 10.69,12.4 13.08,12.4 13.64,12.95 13.64,13.59 12.98,14.25 11.07,14.25 10.19,13.36 10.11,13.36 10.06,13.41 10.06,13.46 10.13,13.54 10.13,14.83 9.96,15.01 9.17,15.01
N12647250 on BOTTOM: 12.29,9.02 11.79,9.53 11.79,10.21 12.75,11.18 16.71,11.18 17.14,11.61 18.44,11.61 18.52,11.53 18.52,10.01 17.53,9.02
N12647255 on BOTTOM: 15.29,12.47 18.34,12.47 18.44,12.57 18.44,13.97 18.92,14.45 18.92,15.82 18.77,15.98 17.53,15.98 17.4,15.85 17.4,15.29 16.59,14.48 14.99,14.48 14.88,14.38 14.88,12.88
N12647291 on BOTTOM: 15.11,22.02 15.11,18.59 15.34,18.36 16.79,18.36 17.4,17.75 18.69,17.75 18.92,17.98 18.92,19.08 18.72,19.28 17.25,19.28 16.64,19.89 16.64,21.92 16.38,22.17 15.27,22.17
N12648519 on TOP: 7.72,14.1 8.15,14.1 8.2,14.15 8.2,14.91 8.84,15.54 9.88,15.54 10.03,15.7 10.03,16.21 9.88,16.36 8.59,16.36 7.62,15.39 7.62,14.2
N12649378 on BOTTOM: 15.42,1.78 15.42,1.6 15.32,1.5 14.27,1.5 13.31,0.53 11.35,0.53 11.18,0.71 11.18,3.17 11.3,3.3 11.66,3.3 11.84,3.12 11.84,2.51 12.37,1.98 13.77,1.98 13.89,1.85 15.34,1.85
N12649481 on BOTTOM: 7.26,1.5 7.26,0.84 7.42,0.69 9.19,0.69 9.4,0.89 9.4,1.55 9.17,1.78 8.23,1.78 8.08,1.63 7.39,1.63
N12651364 on BOTTOM: 0.69,7.04 1.96,7.04 2.08,6.91 2.08,5.26 1.22,4.39 0.56,4.39 0.43,4.52 0.43,6.78
N12652887 on TOP: 40.92,3.73 40.92,2.31 41.07,2.16 42.27,2.16 42.42,2.01 42.42,0.69 42.6,0.51 47.07,0.51 47.22,0.66 47.22,18.77 46.61,19.38 31.62,19.38 31.19,18.95 31.19,16.92 31.83,16.28 43.84,16.28 44.93,15.19 44.93,4.67 44.07,3.81 41,3.81
N12652887 on BOTTOM: 32.94,15.01 32.94,13.64 33.93,12.65 36.53,12.65 39.98,16.1 44.02,16.1 44.93,15.19 44.93,4.67 44.07,3.81 41,3.81 40.92,3.73 40.92,1.78 41.43,1.27 41.43,0.69 41.61,0.51 47.07,0.51 47.22,0.66 47.22,20.55 46.94,20.83 38.76,20.83
N12653157 on BOTTOM (solid shape): 38.13,1.04 34.09,1.04 34.09,5.26 38.13,5.26
N12653157 on TOP: 31.27,2.11 30.76,2.62 29.74,2.62 29.21,2.08 28.17,2.08 27.83,2.43 27.83,3.09 29.32,4.58 29.32,6.39 32.28,9.35 39.83,9.35 40.59,8.59 40.59,2.39 40.31,2.11
N12653157 on BOTTOM: 32.36,0.56 38.1,0.56 38.23,0.69 38.23,5.44 37.67,5.99 37.26,5.99 37.01,6.25 37.01,9.09 36.73,9.37 32.23,9.37 32.05,9.19 32.05,7.04 33.58,5.51 33.58,1.27 33.45,1.14 32.31,1.14 32.23,1.07 32.23,0.69
N12653381 on BOTTOM: 26.11,13.44 26.24,13.56 27.08,13.56 27.36,13.28 28.5,13.28 28.68,13.11 28.68,12.7 28.55,12.57 27.97,12.57 27.58,12.19 27.58,10.41 28.57,9.42 29.01,9.42 29.01,8.99 27.25,8.99 27.25,9.47 26.11,10.62

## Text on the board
Ref Des/Silkscreen Bottom: DER 908 REV A | 2008 | S/N
User.5: SLOT
User.6: 14.  FAB HOUSE LOGO,DATE CODE TO BE IN SILK SCREEN ONLY.DO NOT USE COPPER. | 13.  MATERIAL FR4 COPPER 2oz THICKNESS 0.062"
User.8: FIGURE | FINISHED_SIZE | 18.0 | 20.0 | 24.0 | 25.0 | 30.0 | 40.0 | 48.0 | 52.0 | 68.0 | DRILL CHART: TOP to BOTTOM | ALL UNITS ARE IN MILS | TOLERANCE_DRILL | +3.0/-3.0 | +0.0/-0.0 | PLATED | QTY | 109 | 3 | 1 | 15 | 4 | 2 | 10
